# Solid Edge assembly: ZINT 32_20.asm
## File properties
Title: Zylinder
Author: bmolnar
Template: iso metric assembly.asm
Last saved by: bmolnar
Revision: 13
Application: Solid Edge
Username: bmolnar
Dokumentum tartalom típus: 1
Document Number: ZINT 32/20
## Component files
hrungsstange.par
Profilrohr.par
Platte.par
Kolbenstange.par
Kit_2.par
Kit_1.par
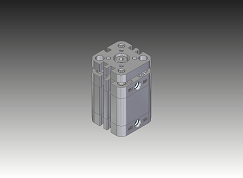
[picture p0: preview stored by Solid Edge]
